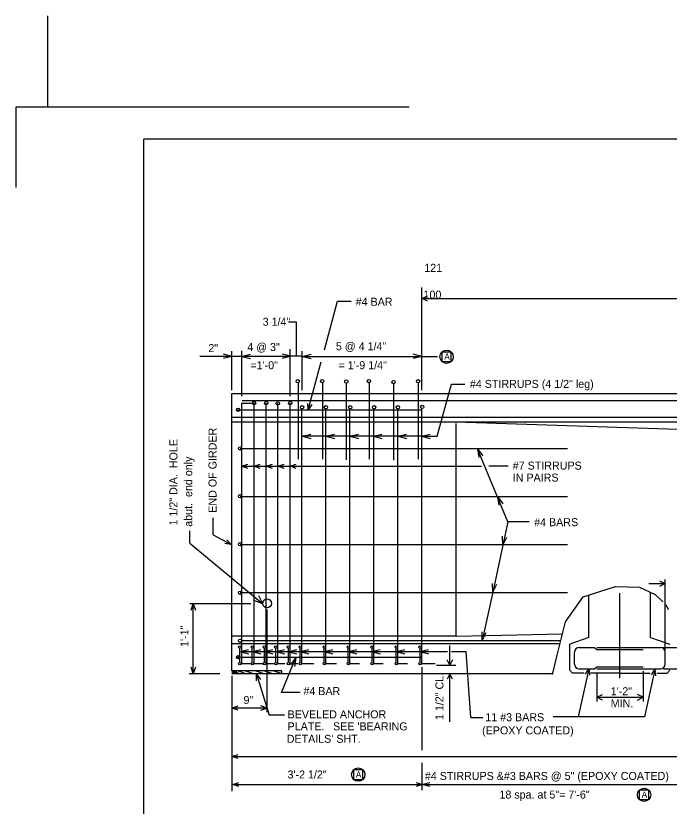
# Model space of a CAD drawing. Extents: x 1005.2 to 1101.8, y 1997.9 to 2073.7.
# Drawn here: x 1008.43 to 1035.67, y 2040.78 to 2073.7 of the extents above; entities that cross this region are included whole.
import ezdxf

# ---------------------------------------------------------------- set-up
doc = ezdxf.new("R2010")
doc.units = 0
for name, color, linetype in [('Level 1', 7, 'Continuous'), ('Level 2', 7, 'Continuous'), ('Level 5', 7, 'Continuous'), ('Level 6', 7, 'Continuous'), ('Level 60', 7, 'Continuous')]:
    doc.layers.add(name, color=color, linetype=linetype)

msp = doc.modelspace()

# ---------------------------------------------------------------- linework, layer by layer
at = {"layer": 'Level 1'}
for p, q in [((1024.831, 2069.894), (1008.43, 2069.894)), ((1008.43, 2069.894), (1008.43, 2066.554)), ((1013.763, 2012.562), (1013.763, 2068.561)), ((1097.431, 2068.561), (1013.763, 2068.561))]:
    msp.add_line(p, q, dxfattribs=at)
at = {"layer": 'Level 2'}
for p, q in [((1009.763, 2069.894), (1009.763, 2073.698)), ((1025.357, 2058.113), (1025.357, 2062.376)), ((1021.298, 2059.783), (1021.846, 2061.808)), ((1021.846, 2061.808), (1022.41, 2061.808)), ((1025.357, 2061.923), (1054.324, 2061.923)), ((1020.13, 2060.939), (1019.792, 2060.939)), ((1020.13, 2059.522), (1020.13, 2060.939)), ((1019.87, 2057.862), (1019.87, 2059.809)), ((1017.857, 2059.514), (1016.107, 2059.514)), ((1017.441, 2059.514), (1016.171, 2059.514)), ((1017.441, 2059.514), (1017.081, 2059.604)), ((1017.441, 2059.514), (1017.081, 2059.424)), ((1017.441, 2058.106), (1017.441, 2059.732)), ((1017.857, 2057.854), (1017.857, 2059.744)), ((1017.857, 2059.514), (1018.217, 2059.604)), ((1019.87, 2059.514), (1017.857, 2059.514)), ((1017.857, 2059.514), (1018.217, 2059.424)), ((1019.898, 2059.522), (1019.538, 2059.612)), ((1019.898, 2059.522), (1019.538, 2059.432)), ((1020.36, 2059.522), (1019.87, 2059.522)), ((1020.36, 2058.103), (1020.36, 2059.725)), ((1020.36, 2059.514), (1026.005, 2059.514)), ((1020.375, 2059.514), (1020.735, 2059.604)), ((1020.375, 2059.514), (1020.735, 2059.424)), ((1025.357, 2059.514), (1024.997, 2059.604)), ((1025.357, 2059.514), (1024.997, 2059.424)), ((1020.621, 2057.286), (1021.163, 2059.286)), ((1026.195, 2059.303), (1026.195, 2059.303)), ((1020.194, 2058.425), (1020.194, 2055.229)), ((1021.21, 2058.425), (1021.21, 2055.229)), ((1022.207, 2058.404), (1022.207, 2055.208)), ((1023.161, 2058.425), (1023.161, 2055.229)), ((1024.178, 2058.383), (1024.178, 2055.187)), ((1025.195, 2058.425), (1025.195, 2055.229)), ((1025.994, 2056.185), (1026.584, 2058.362)), ((1026.584, 2058.362), (1027.147, 2058.362)), ((1017.441, 2046.413), (1017.441, 2057.969)), ((1017.441, 2057.969), (1038.737, 2057.969)), ((1017.857, 2057.562), (1018.382, 2057.562)), ((1017.857, 2047.379), (1017.857, 2057.562)), ((1017.863, 2057.676), (1031.429, 2057.676)), ((1018.362, 2046.728), (1018.362, 2057.562)), ((1018.87, 2046.728), (1018.87, 2057.562)), ((1019.357, 2046.728), (1019.357, 2057.562)), ((1019.87, 2046.728), (1019.87, 2057.562)), ((1031.429, 2057.676), (1038.745, 2057.676)), ((1017.64, 2057.286), (1025.357, 2057.286)), ((1020.357, 2046.728), (1020.357, 2057.335)), ((1021.357, 2046.728), (1021.357, 2057.335)), ((1022.357, 2046.728), (1022.357, 2057.325)), ((1023.357, 2046.728), (1023.357, 2057.335)), ((1024.357, 2046.728), (1024.357, 2057.325)), ((1025.357, 2046.728), (1025.357, 2057.335)), ((1038.745, 2056.969), (1017.439, 2056.969)), ((1038.737, 2056.772), (1017.426, 2056.772)), ((1038.441, 2056.386), (1026.782, 2056.772)), ((1026.782, 2047.859), (1026.782, 2056.719)), ((1020.374, 2056.185), (1020.734, 2056.275)), ((1022.351, 2056.185), (1020.374, 2056.185)), ((1020.374, 2056.185), (1020.734, 2056.095)), ((1021.349, 2056.185), (1021.709, 2056.275)), ((1021.349, 2056.185), (1021.709, 2056.095)), ((1022.351, 2056.185), (1022.711, 2056.275)), ((1023.284, 2056.185), (1022.351, 2056.185)), ((1022.351, 2056.185), (1022.711, 2056.095)), ((1023.333, 2056.185), (1023.284, 2056.185)), ((1023.333, 2056.185), (1023.693, 2056.275)), ((1024.362, 2056.185), (1023.333, 2056.185)), ((1023.333, 2056.185), (1023.693, 2056.095)), ((1024.362, 2056.185), (1024.722, 2056.275)), ((1025.347, 2056.185), (1024.362, 2056.185)), ((1024.362, 2056.185), (1024.722, 2056.095)), ((1025.347, 2056.185), (1025.707, 2056.275)), ((1025.347, 2056.185), (1025.994, 2056.185)), ((1025.347, 2056.185), (1025.707, 2056.095)), ((1017.78, 2055.676), (1031.429, 2055.676)), ((1028.945, 2052.627), (1027.669, 2055.663)), ((1027.669, 2055.663), (1027.892, 2055.366)), ((1027.669, 2055.663), (1027.726, 2055.296)), ((1017.842, 2054.936), (1027.842, 2054.936)), ((1028.958, 2054.936), (1028.149, 2054.936)), ((1017.78, 2053.676), (1031.429, 2053.676)), ((1028.504, 2053.676), (1028.726, 2053.379)), ((1028.504, 2053.676), (1028.561, 2053.31)), ((1016.66, 2052.086), (1016.66, 2052.795)), ((1028.945, 2052.627), (1028.735, 2051.653)), ((1029.834, 2052.627), (1028.945, 2052.627)), ((1016.66, 2052.086), (1017.41, 2051.679)), ((1028.735, 2051.653), (1028.723, 2052.024)), ((1028.735, 2051.653), (1028.899, 2051.986)), ((1017.78, 2051.676), (1031.429, 2051.676)), ((1028.735, 2051.653), (1028.311, 2049.688)), ((1035.494, 2047.271), (1035.494, 2050.224)), ((1028.311, 2049.688), (1028.299, 2050.059)), ((1028.311, 2049.688), (1028.475, 2050.021)), ((1034.813, 2050.053), (1035.494, 2050.053)), ((1017.78, 2049.676), (1023.804, 2049.676)), ((1023.804, 2049.676), (1031.429, 2049.676)), ((1028.311, 2049.688), (1027.876, 2047.676)), ((1032.321, 2047.81), (1032.321, 2049.575)), ((1033.607, 2046.105), (1033.607, 2049.645)), ((1034.892, 2047.81), (1034.892, 2049.686)), ((1026.782, 2047.859), (1031.222, 2047.964)), ((1027.876, 2047.676), (1027.864, 2048.047)), ((1027.876, 2047.676), (1028.04, 2048.009)), ((1026.782, 2047.859), (1017.441, 2047.859)), ((1017.85, 2047.676), (1031.149, 2047.676)), ((1032.321, 2047.81), (1031.518, 2047.528)), ((1034.892, 2047.81), (1035.695, 2047.528)), ((1017.44, 2047.552), (1031.118, 2047.552)), ((1017.769, 2046.782), (1017.769, 2047.355)), ((1017.769, 2047.216), (1018.129, 2047.306)), ((1017.857, 2046.728), (1017.857, 2047.379)), ((1018.28, 2047.216), (1018.64, 2047.306)), ((1018.284, 2046.782), (1018.284, 2047.355)), ((1018.789, 2047.216), (1019.149, 2047.306)), ((1018.793, 2046.782), (1018.793, 2047.355)), ((1019.265, 2047.216), (1019.625, 2047.306)), ((1019.271, 2046.782), (1019.271, 2047.355)), ((1019.79, 2047.215), (1020.15, 2047.305)), ((1019.793, 2046.782), (1019.793, 2047.355)), ((1020.283, 2047.216), (1020.643, 2047.306)), ((1020.286, 2046.782), (1020.286, 2047.355)), ((1021.289, 2046.782), (1021.289, 2047.355)), ((1021.29, 2047.216), (1021.65, 2047.306)), ((1022.289, 2046.782), (1022.289, 2047.379)), ((1022.289, 2047.216), (1022.649, 2047.306)), ((1023.258, 2047.216), (1023.618, 2047.306)), ((1023.278, 2046.782), (1023.278, 2047.379)), ((1024.289, 2046.782), (1024.289, 2047.379)), ((1024.289, 2047.216), (1024.649, 2047.306)), ((1025.274, 2047.22), (1025.634, 2047.31)), ((1025.284, 2046.782), (1025.284, 2047.379)), ((1026.512, 2047.469), (1026.512, 2046.649)), ((1031.518, 2046.444), (1031.518, 2047.528)), ((1031.912, 2047.388), (1032.556, 2047.388)), ((1032.556, 2047.388), (1032.651, 2047.311)), ((1032.651, 2047.388), (1035.302, 2047.388)), ((1032.651, 2047.311), (1034.583, 2047.311)), ((1035.41, 2047.388), (1037.062, 2047.388)), ((1017.64, 2046.986), (1025.357, 2046.986)), ((1017.769, 2047.216), (1018.53, 2047.216)), ((1017.769, 2047.216), (1018.129, 2047.126)), ((1018.28, 2047.216), (1018.64, 2047.126)), ((1018.53, 2047.216), (1019.251, 2047.216)), ((1018.789, 2047.216), (1019.149, 2047.126)), ((1019.251, 2047.216), (1020.274, 2047.216)), ((1019.265, 2047.216), (1019.625, 2047.126)), ((1019.499, 2045.521), (1020.103, 2046.973)), ((1019.79, 2047.215), (1020.15, 2047.125)), ((1020.099, 2046.971), (1019.877, 2046.673)), ((1020.099, 2046.971), (1020.043, 2046.604)), ((1020.274, 2047.216), (1021.29, 2047.216)), ((1020.283, 2047.216), (1020.643, 2047.126)), ((1021.29, 2047.216), (1023.258, 2047.216)), ((1021.29, 2047.216), (1021.65, 2047.126)), ((1022.289, 2047.216), (1022.649, 2047.126)), ((1023.258, 2047.216), (1025.358, 2047.216)), ((1023.258, 2047.216), (1023.618, 2047.126)), ((1024.289, 2047.216), (1024.649, 2047.126)), ((1025.274, 2047.22), (1025.634, 2047.13)), ((1025.358, 2047.216), (1026.419, 2047.216)), ((1026.595, 2047.216), (1027.202, 2047.216)), ((1027.399, 2044.471), (1027.202, 2047.216)), ((1031.719, 2046.697), (1031.719, 2047.195)), ((1035.494, 2046.697), (1035.494, 2047.195)), ((1017.857, 2046.728), (1017.857, 2046.765)), ((1017.857, 2046.728), (1018.202, 2046.728)), ((1018.362, 2046.728), (1018.706, 2046.728)), ((1018.87, 2046.728), (1019.174, 2046.728)), ((1019.357, 2046.728), (1019.648, 2046.728)), ((1019.87, 2046.728), (1020.186, 2046.728)), ((1020.357, 2046.728), (1020.851, 2046.728)), ((1021.357, 2046.728), (1021.793, 2046.728)), ((1022.359, 2046.728), (1022.762, 2046.728)), ((1023.357, 2046.728), (1023.743, 2046.728)), ((1024.364, 2046.728), (1024.762, 2046.728)), ((1025.357, 2046.728), (1025.906, 2046.728)), ((1025.97, 2046.649), (1026.774, 2046.649)), ((1032.556, 2046.504), (1032.651, 2046.587)), ((1032.651, 2046.587), (1034.583, 2046.587)), ((1017.441, 2046.413), (1017.769, 2046.301)), ((1017.769, 2046.302), (1030.816, 2046.302)), ((1025.357, 2046.576), (1025.357, 2043.109)), ((1026.512, 2046.302), (1026.512, 2044.294)), ((1026.834, 2046.302), (1026.901, 2046.302)), ((1031.639, 2046.323), (1031.518, 2046.444)), ((1032.126, 2046.323), (1031.639, 2046.323)), ((1032.311, 2046.503), (1031.873, 2044.502)), ((1031.912, 2046.504), (1032.556, 2046.504)), ((1033.607, 2046.323), (1032.385, 2046.323)), ((1032.651, 2046.504), (1035.302, 2046.504)), ((1032.651, 2046.326), (1032.651, 2045.141)), ((1033.607, 2046.323), (1034.875, 2046.323)), ((1034.583, 2046.409), (1034.583, 2045.141)), ((1035.062, 2046.474), (1034.63, 2044.502)), ((1035.156, 2046.323), (1035.575, 2046.323)), ((1035.43, 2046.504), (1037.062, 2046.504)), ((1035.575, 2046.323), (1035.695, 2046.444)), ((1017.441, 2046.208), (1017.441, 2041.404)), ((1020.283, 2045.521), (1019.499, 2045.521)), ((1032.651, 2045.319), (1034.583, 2045.319)), ((1027.399, 2044.471), (1027.892, 2044.471)), ((1034.63, 2044.502), (1030.834, 2044.502)), ((1017.441, 2042.85), (1061.731, 2042.85)), ((1025.357, 2042.592), (1025.357, 2041.445)), ((1017.463, 2041.684), (1025.357, 2041.684)), ((1022.511, 2041.897), (1022.511, 2041.897)), ((1025.357, 2041.684), (1037.408, 2041.684)), ((1034.424, 2041.056), (1034.424, 2041.056))]:
    msp.add_line(p, q, dxfattribs=at)
for points in [[(1025.59, 2061.815), (1025.368, 2061.926), (1025.59, 2062.037)], [(1020.772, 2057.507), (1020.621, 2057.286), (1020.603, 2057.553)], [(1018.095, 2054.848), (1017.842, 2054.936), (1018.095, 2055.024)], [(1018.614, 2054.848), (1018.361, 2054.936), (1018.614, 2055.024)], [(1019.123, 2054.848), (1018.87, 2054.936), (1019.123, 2055.024)], [(1019.611, 2054.848), (1019.357, 2054.936), (1019.611, 2055.024)], [(1020.123, 2054.848), (1019.87, 2054.936), (1020.123, 2055.024)], [(1017.229, 2051.877), (1017.41, 2051.679), (1017.145, 2051.723)], [(1030.807, 2046.261), (1030.995, 2047.069), (1031.348, 2048.459), (1032.076, 2049.496), (1033.422, 2049.93), (1034.422, 2049.9), (1035.084, 2049.599), (1035.406, 2049.287)], [(1035.256, 2050.172), (1035.494, 2050.053), (1035.256, 2049.934)], [(1035.636, 2048.954), (1035.532, 2049.167)], [(1026.628, 2046.869), (1026.517, 2046.647), (1026.406, 2046.869)], [(1026.634, 2046.071), (1026.523, 2046.293), (1026.411, 2046.071)], [(1032.171, 2046.274), (1032.311, 2046.503), (1032.343, 2046.237)], [(1034.922, 2046.245), (1035.062, 2046.474), (1035.093, 2046.207)], [(1032.889, 2045.2), (1032.651, 2045.319), (1032.889, 2045.438)], [(1034.345, 2045.2), (1034.583, 2045.319), (1034.345, 2045.438)], [(1017.694, 2042.763), (1017.441, 2042.85), (1017.694, 2042.938)], [(1017.724, 2041.597), (1017.471, 2041.684), (1017.724, 2041.772)], [(1025.124, 2041.772), (1025.378, 2041.684), (1025.124, 2041.597)], [(1025.691, 2041.601), (1025.357, 2041.684), (1025.691, 2041.768)]]:
    msp.add_lwpolyline(points, dxfattribs=at)
for points in [[(1026.191, 2059.694), (1026.191, 2059.302), (1026.583, 2059.302), (1026.583, 2059.694)], [(1022.506, 2042.288), (1022.506, 2041.895), (1022.898, 2041.895), (1022.898, 2042.288)], [(1034.419, 2041.447), (1034.419, 2041.055), (1034.812, 2041.055), (1034.812, 2041.447)]]:
    msp.add_lwpolyline(points, close=True, dxfattribs=at)
for centre, radius in [((1026.388, 2059.499), 0.277), ((1020.184, 2058.477), 0.0694), ((1021.203, 2058.487), 0.0694), ((1022.202, 2058.467), 0.0694), ((1023.149, 2058.487), 0.0694), ((1024.178, 2058.446), 0.0694), ((1025.198, 2058.477), 0.0694), ((1018.362, 2057.568), 0.0694), ((1018.871, 2057.568), 0.0694), ((1019.352, 2057.558), 0.0694), ((1019.871, 2057.568), 0.0694), ((1020.36, 2057.397), 0.0694), ((1021.358, 2057.397), 0.0694), ((1022.372, 2057.397), 0.0694), ((1023.366, 2057.397), 0.0694), ((1024.359, 2057.397), 0.0694), ((1025.375, 2057.408), 0.0694), ((1017.697, 2057.288), 0.0694), ((1017.781, 2055.681), 0.0694), ((1017.781, 2053.689), 0.0694), ((1017.781, 2051.688), 0.0694), ((1017.781, 2049.669), 0.0694), ((1017.781, 2047.668), 0.0694), ((1017.767, 2047.407), 0.052), ((1018.287, 2047.407), 0.052), ((1018.796, 2047.407), 0.052), ((1019.269, 2047.407), 0.052), ((1019.796, 2047.407), 0.052), ((1020.287, 2047.407), 0.052), ((1021.291, 2047.407), 0.052), ((1022.291, 2047.407), 0.052), ((1023.274, 2047.407), 0.052), ((1024.291, 2047.407), 0.052), ((1025.286, 2047.407), 0.052), ((1017.697, 2046.984), 0.0694), ((1017.767, 2046.713), 0.052), ((1018.287, 2046.713), 0.052), ((1018.796, 2046.713), 0.052), ((1019.269, 2046.713), 0.052), ((1019.796, 2046.713), 0.052), ((1020.287, 2046.713), 0.052), ((1021.291, 2046.713), 0.052), ((1022.291, 2046.713), 0.052), ((1023.282, 2046.713), 0.052), ((1024.291, 2046.713), 0.052), ((1025.286, 2046.713), 0.052), ((1022.703, 2042.093), 0.277), ((1034.617, 2041.252), 0.277)]:
    msp.add_circle(centre, radius, dxfattribs=at)
for centre, start, end in [((1031.912, 2047.195), 90, 180), ((1035.302, 2047.195), 0, 90), ((1031.912, 2046.697), 180, 270), ((1035.302, 2046.697), 270, 0)]:
    msp.add_arc(centre, 0.193, start, end, dxfattribs=at)
at = {"layer": 'Level 5'}
for p, q in [((1015.685, 2051.734), (1015.685, 2052.253)), ((1015.685, 2051.734), (1018.731, 2049.207)), ((1018.731, 2049.207), (1018.349, 2049.352)), ((1018.731, 2049.207), (1018.562, 2049.539)), ((1018.232, 2049.203), (1015.688, 2049.203)), ((1015.829, 2046.311), (1015.829, 2049.201)), ((1018.888, 2048.97), (1018.888, 2044.7)), ((1016.94, 2046.287), (1015.65, 2046.287)), ((1018.888, 2044.867), (1017.441, 2044.867))]:
    msp.add_line(p, q, dxfattribs=at)
for points in [[(1015.741, 2048.948), (1015.829, 2049.201), (1015.916, 2048.948)], [(1015.741, 2048.948), (1015.829, 2049.201), (1015.916, 2048.948)], [(1015.916, 2046.565), (1015.829, 2046.311), (1015.741, 2046.565)], [(1017.694, 2044.779), (1017.441, 2044.867), (1017.694, 2044.955)], [(1018.641, 2044.779), (1018.894, 2044.867), (1018.641, 2044.955)]]:
    msp.add_lwpolyline(points, dxfattribs=at)
msp.add_circle((1018.906, 2049.225), 0.186, dxfattribs=at)
at = {"layer": 'Level 6'}
for p, q in [((1017.609, 2046.413), (1017.441, 2046.413)), ((1017.441, 2046.405), (1017.609, 2046.405)), ((1017.441, 2046.395), (1017.609, 2046.395)), ((1017.441, 2046.385), (1017.609, 2046.385)), ((1017.441, 2046.375), (1017.609, 2046.375)), ((1017.441, 2046.365), (1017.609, 2046.365)), ((1017.441, 2046.355), (1017.609, 2046.355)), ((1017.441, 2046.345), (1017.609, 2046.345)), ((1017.441, 2046.335), (1017.609, 2046.335)), ((1017.441, 2046.325), (1017.609, 2046.325)), ((1017.441, 2046.315), (1017.609, 2046.315)), ((1017.441, 2046.305), (1017.609, 2046.305)), ((1017.609, 2046.302), (1017.441, 2046.302)), ((1017.698, 2046.413), (1018.025, 2046.302)), ((1017.999, 2046.413), (1018.327, 2046.301)), ((1018.44, 2046.41), (1018.768, 2046.299)), ((1018.466, 2046.274), (1018.99, 2044.573)), ((1018.803, 2046.413), (1019.131, 2046.302)), ((1019.188, 2046.415), (1019.515, 2046.304)), ((1019.632, 2044.573), (1018.99, 2044.573))]:
    msp.add_line(p, q, dxfattribs=at)
msp.add_lwpolyline([(1019.518, 2046.413), (1017.609, 2046.413), (1017.609, 2046.302), (1019.518, 2046.302)], close=True, dxfattribs=at)
msp.add_lwpolyline([(1018.457, 2046.006), (1018.466, 2046.274), (1018.625, 2046.058)], dxfattribs=at)

# ---------------------------------------------------------------- texts
at = {"layer": 'Level 2'}
for s, height, p in [('#4 BAR', 0.3333, (1022.597, 2061.623)), ('3 1/4"', 0.3333, (1018.72, 2060.79)), ('4 @ 3"', 0.3333, (1018.079, 2059.738)), ('5 @ 4 1/4"', 0.3333, (1021.773, 2059.767)), ('2"', 0.3333, (1016.454, 2059.691)), ('A', 0.261, (1026.288, 2059.374)), ('=1\'-0"', 0.3333, (1018.209, 2058.979)), ('= 1\'-9 1/4"', 0.33333, (1021.882, 2058.979)), ('#4 STIRRUPS (4 1/2" leg)', 0.33333, (1027.357, 2058.2)), ('#7 STIRRUPS', 0.33333, (1029.145, 2054.799)), ('IN PAIRS', 0.3333, (1029.145, 2054.299)), ('#4 BARS', 0.3333, (1030.036, 2052.441)), ('#4 BAR', 0.3333, (1020.418, 2045.406)), ('1\'-2"', 0.3333, (1033.228, 2045.4)), ('MIN.', 0.3333, (1033.228, 2044.9)), ('11 #3 BARS', 0.3333, (1028, 2044.319)), ('(EPOXY COATED)', 0.33333, (1027.867, 2043.77)), ('3\'-2 1/2"', 0.3333, (1019.756, 2041.933)), ('A', 0.261, (1022.603, 2041.967)), ('#4 STIRRUPS &#3 BARS @ 5" (EPOXY COATED)', 0.33333, (1025.48, 2041.872)), ('18 spa. at 5"= 7\'-6"', 0.33333, (1028.59, 2041.097)), ('A', 0.261, (1034.517, 2041.127))]:
    msp.add_text(s, height=height, dxfattribs=at).set_placement(p)
for s, height, p in [('END OF GIRDER', 0.33333, (1016.797, 2053.001)), ('1 1/2" CL.', 0.3333, (1026.254, 2044.367))]:
    msp.add_text(s, height=height, rotation=90, dxfattribs=at).set_placement(p)
at = {"layer": 'Level 5'}
for s, height, p in [('1 1/2" DIA.  HOLE', 0.33333, (1015.167, 2052.47)), ('abut.  end only', 0.33333, (1015.783, 2052.417)), ('1\'-1"', 0.3333, (1015.626, 2047.411))]:
    msp.add_text(s, height=height, rotation=90, dxfattribs=at).set_placement(p)
msp.add_text('9"', height=0.3333, dxfattribs=at).set_placement((1017.92, 2045.033))
at = {"layer": 'Level 6'}
for s, height, p in [('BEVELED ANCHOR', 0.33333, (1019.759, 2044.438)), ("SEE 'BEARING", 0.33333, (1021.654, 2043.938)), ('PLATE.', 0.3333, (1019.759, 2043.938)), ("DETAILS' SHT.", 0.33333, (1019.724, 2043.419))]:
    msp.add_text(s, height=height, dxfattribs=at).set_placement(p)
at = {"layer": 'Level 60'}
for s, p in [('121', (1025.457, 2063.035)), ('100', (1025.425, 2061.918))]:
    msp.add_text(s, height=0.3333, dxfattribs=at).set_placement(p)

doc.saveas('drawing.dxf')
